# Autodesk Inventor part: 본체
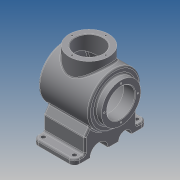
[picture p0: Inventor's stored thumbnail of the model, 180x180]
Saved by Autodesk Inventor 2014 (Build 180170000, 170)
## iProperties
Created: 2018-08
Part Number: 본체
Material: Generic
Document SubType Name: Modeling
Designer: kb542
Density: 1 g/cm^3
Appearance: Default
Author: kb542
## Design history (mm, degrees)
sketch "스케치1"
  geometry: L1 (-48, 50)-(48.671, 50); L2 (-48, 50)-(-48, 38); L3 (-48, 38)-(-60, 38); L4 (-60, 38)-(-60, 27); L5 (-60, 27)-(-38, 27); L6 (-38, 27)-(-38, 40); L7 (-38, 40)-(42.163, 40); L8 (-60, 0)-(60, 0); A1 r 116 centre (-56, 0) between (60, 0) and (48.671, 50); A2 r 106 centre (-56, 0) between (50, 0) and (42.163, 40); 2 further points
  constraints: 16 end point, 4 parallel, 4 point on circle, 2 centre point, 2 horizontal, 2 perpendicular, 2 point on line, 1 coincident, 1 midpoint, 1 vertical alignment
  dimensions: "d0" = 120 distance of L8.end L8.start; "d4" = 10 radial gap between concentric circles of A1 A2; "d5" = 80 diameter of L7 L8; "d6" = 100 diameter of L1 L8; "d7" = 76 diameter of L3 L8; "d8" = 54 diameter of L5 L8; "d9" = 12 distance of L2.end L3.end; "d10" = 22 distance of L4.end L5.end; "d12" = 116 radius of A1
revolve "회전1" sketch "스케치1" stored, may be unused: angle "d13" = 90 deg
node "작업 평면1"
sketch "스케치2"
  geometry: L1 (40, -70)-(-40, -70); L2 (-40, -70)-(-40, 70); L3 (-40, 70)-(40, 70); L4 (40, 70)-(40, -70); L5 (48, 50)-(48, -50) reference; 2 further points
  constraints: 8 end point, 2 parallel, 1 horizontal, 1 horizontal alignment, 1 midpoint, 1 perpendicular
  dimensions: "d15" = 80 distance of L1.start L1.end; "d16" = 140 distance of L1.end L2.end; "d17" = 8 distance between parallel lines of L4 L5
extrude "돌출1" join sketch "스케치2" distance "d18" = 10; taper "d19" = 0 deg
sketch "스케치3"
  geometry: L1 (70, -72)-(-70, -72) reference; L2 (-50, -72)-(-50, -43.437); L3 (50, -72)-(50, -43.437); L4 (70, -82)-(70, -72) reference; L5 (-70, -82)-(-70, -72) reference; L6 (70, -72)-(40.304, -29.59); L7 (-70, -72)-(-40.304, -29.59); L8 (-50, -72)-(50, -72); A1 r 50 centre (0, 0) between (40.304, -29.59) and (-40.304, -29.59) reference; 1 further point
  constraints: 10 end point, 4 point on line, 2 point on circle, 1 collinear, 1 parallel, 1 perpendicular
  dimensions: "d20" = 20 distance between parallel lines of L4 L3; "d21" = 20 distance between parallel lines of L2 L5; "d24" = 35 deg angle of L6 L4; "d26" = 35 deg angle of L7 L5
extrude "돌출2" join sketch "스케치3" stored distance "d27" = 80; taper "d28" = 0 deg
sketch "스케치4"
  geometry: L1 (0, 0)-(0, 140) reference; A1 r 50 centre (82, 70) between (52.41, 110.304) and (52.41, 29.696) reference; A2 r 12.5 centre (0, 97.5) between (0, 85) and (0, 110); A3 r 17.5 centre (0, 47.5) between (0, 30) and (0, 65)
  constraints: 6 point on line, 4 point on circle, 2 centre point
  dimensions: "d31" = 12.5 radius of A2; "d32" = 17.5 radius of A3; "d33" = 27.5 vertical distance of A2.centre A1.centre; "d34" = 22.5 vertical distance of A3.centre A1.centre
extrude "돌출3" cut sketch "스케치4" stored distance "d35" = 80; taper "d36" = 0 deg
fillet "모깎기1" dims "d37" = 10
hole "구멍1" diameter "d40" = 8; stored, may be unused: countersink angle "d44" = 90 deg, drill point angle "d46" = 118 deg; dims "d38" = 10, "d39" = 10, "d41" = 6, "d42" = 4, "d43" = 2, "d45" = 8
hole "구멍2" diameter "d49" = 8; stored, may be unused: countersink angle "d53" = 90 deg, drill point angle "d55" = 118 deg; dims "d47" = 10, "d48" = 10, "d50" = 6, "d51" = 4, "d52" = 2, "d54" = 8
hole "구멍3" diameter "d58" = 8; stored, may be unused: countersink angle "d62" = 90 deg, drill point angle "d64" = 118 deg; dims "d56" = 10, "d57" = 10, "d59" = 6, "d60" = 4, "d61" = 2, "d63" = 8
hole "구멍4" diameter "d67" = 8; stored, may be unused: countersink angle "d71" = 90 deg, drill point angle "d73" = 118 deg; dims "d65" = 10, "d66" = 10, "d68" = 6, "d69" = 4, "d70" = 2, "d72" = 8
node "작업 평면2"
sketch "스케치5"
  geometry: L1 (48, 50)-(48, -50) reference; C1 r 38 at (-2, 0); 1 further point
  constraints: 1 centre point, 1 horizontal alignment
  dimensions: "d75" = 76 diameter of C1; "d76" = 50 distance from line of C1.centre L1
extrude "돌출4" join sketch "스케치5" stored distance "d77" = 80; taper "d78" = 0 deg
hole "구멍5" diameter "d81" = 54; stored, may be unused: countersink angle "d85" = 90 deg, drill point angle "d87" = 118 deg; dims "d79" = 10, "d80" = 10, "d82" = 6, "d83" = 4, "d84" = 2, "d86" = 8
sketch "스케치6"
  geometry: C1 r 38 at (0, 0) reference; 1 further point
  constraints: 1 horizontal alignment
  dimensions: "d88" = 32.5 distance of C1.centre point (-32.5, 0)
hole "구멍6" sketch "스케치6" at (-32.5, 0) diameter "d89" = 3.242; stored, may be unused: countersink angle "d93" = 90 deg, drill point angle "d95" = 118 deg; dims "d90" = 8, "d91" = 4, "d92" = 2, "d94" = 10
sketch "스케치7"
  geometry: C1 r 27 at (0, 0) reference; 2 further points
  constraints: 1 vertical alignment
  dimensions: "d99" = 32.5 distance of C1.centre point (0, -32.5)
hole "구멍7" sketch "스케치7" at (0, -32.5) diameter "d100" = 3.242; stored, may be unused: countersink angle "d104" = 90 deg, drill point angle "d106" = 118 deg; dims "d101" = 8, "d102" = 4, "d103" = 2, "d105" = 10
chamfer "모따기1" distance "d110" = 1; stored, may be unused: second distance "d111" = 2, angle "d112" = 45 deg
fillet "모깎기2" dims "d113" = 3
fillet "모깎기3" dims "d114" = 3
fillet "모깎기4" dims "d115" = 3
fillet "모깎기5" dims "d116" = 3
fillet "모깎기6" dims "d117" = 3
node "작업 평면3"
sketch "스케치8"
  geometry: C1 r 32.5 at (0, 0); 1 further point
  constraints: 1 centre point, 1 coincident, 1 other
  dimensions: "d118" = 65 diameter of C1
feature "엠보싱1" sketch "스케치8" dims "d119" = 0.5, "d120" = 0
node "솔리드1"
pattern_circular "원형 패턴1" dims angle "d97" = 360 deg
pattern_circular "원형 패턴2" dims angle "d108" = 360 deg
other parameters: "d14" = -82, "d74" = -147
